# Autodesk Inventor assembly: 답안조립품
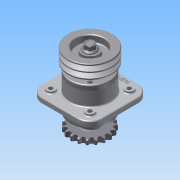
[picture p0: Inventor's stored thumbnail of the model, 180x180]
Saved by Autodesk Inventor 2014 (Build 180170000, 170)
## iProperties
Created: 2015-09
Part Number: 답안조립품
Document SubType Name: Assembly
Designer: study
Author: study
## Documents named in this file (12)
- C:\Users\study\Desktop\450909V1005\답안조립품.iam
- C:\Users\study\Desktop\450909V1005\1-본체.ipt
- C:\Users\study\Desktop\450909V1005\6-베어링 6206.ipt
- C:\Users\study\Desktop\450909V1005\2-커버.ipt
- C:\Users\study\Desktop\450909V1005\8-오일실 30x42.ipt
- C:\Users\study\Desktop\450909V1005\3-축.ipt
- C:\Users\study\Desktop\450909V1005\11-키 6x6.ipt
- C:\Users\study\Desktop\450909V1005\4-V벨트풀리.ipt
- C:\Users\study\Desktop\450909V1005\5-체인 스프로킷.ipt
- C:\Users\study\Desktop\450909V1005\9-M16-너트.ipt
- C:\Users\study\Desktop\450909V1005\10-M6.ipt
- C:\Users\study\Desktop\450909V1005\7-부시.ipt
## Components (23 placed, 11 different names)
1. 1-본체:1
2. 6-베어링 6206:1
3. 6-베어링 6206:2
4. 2-커버:1
5. 2-커버:2
6. 8-8-오일실 30x42:1
7. 8-8-오일실 30x42:2
8. 3-축:1 — 각도:1, 각도:2, 각도:5, 각도:6
9. 11-키 6x6:1 — 각도:1, 각도:3
10. 11-키 6x6:2 — 각도:2, 각도:4
11. 4-V벨트풀리:1 — 각도:3
12. 5-체인 스프로킷:1 — 각도:4
13. 9-M16 너트:1 — 각도:6
14. 9-M16 너트:2 — 각도:5
15. 7-부시:1
16. 10-M6:1
17. 10-M6:3
18. 10-M6:4
19. 10-M6:5
20. 10-M6:2
21. 10-M6:6
22. 10-M6:7
23. 10-M6:8
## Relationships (6: Angle 6)
- 각도:1 [Angle]: 3-축:1 ↔ 11-키 6x6:1
- 각도:2 [Angle]: 3-축:1 ↔ 11-키 6x6:2
- 각도:3 [Angle]: 11-키 6x6:1 ↔ 4-V벨트풀리:1
- 각도:4 [Angle]: 11-키 6x6:2 ↔ 5-체인 스프로킷:1
- 각도:5 [Angle]: 3-축:1 ↔ 9-M16 너트:2
- 각도:6 [Angle]: 3-축:1 ↔ 9-M16 너트:1
